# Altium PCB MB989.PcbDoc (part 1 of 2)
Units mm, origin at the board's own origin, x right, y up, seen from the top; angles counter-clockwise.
Board outline 88.27 x 52.07 mm, 2 copper layers (Top Layer, Bottom Layer), stack 1.6 mm thick; 68 components, 52 nets, 227 pads, 143 vias.
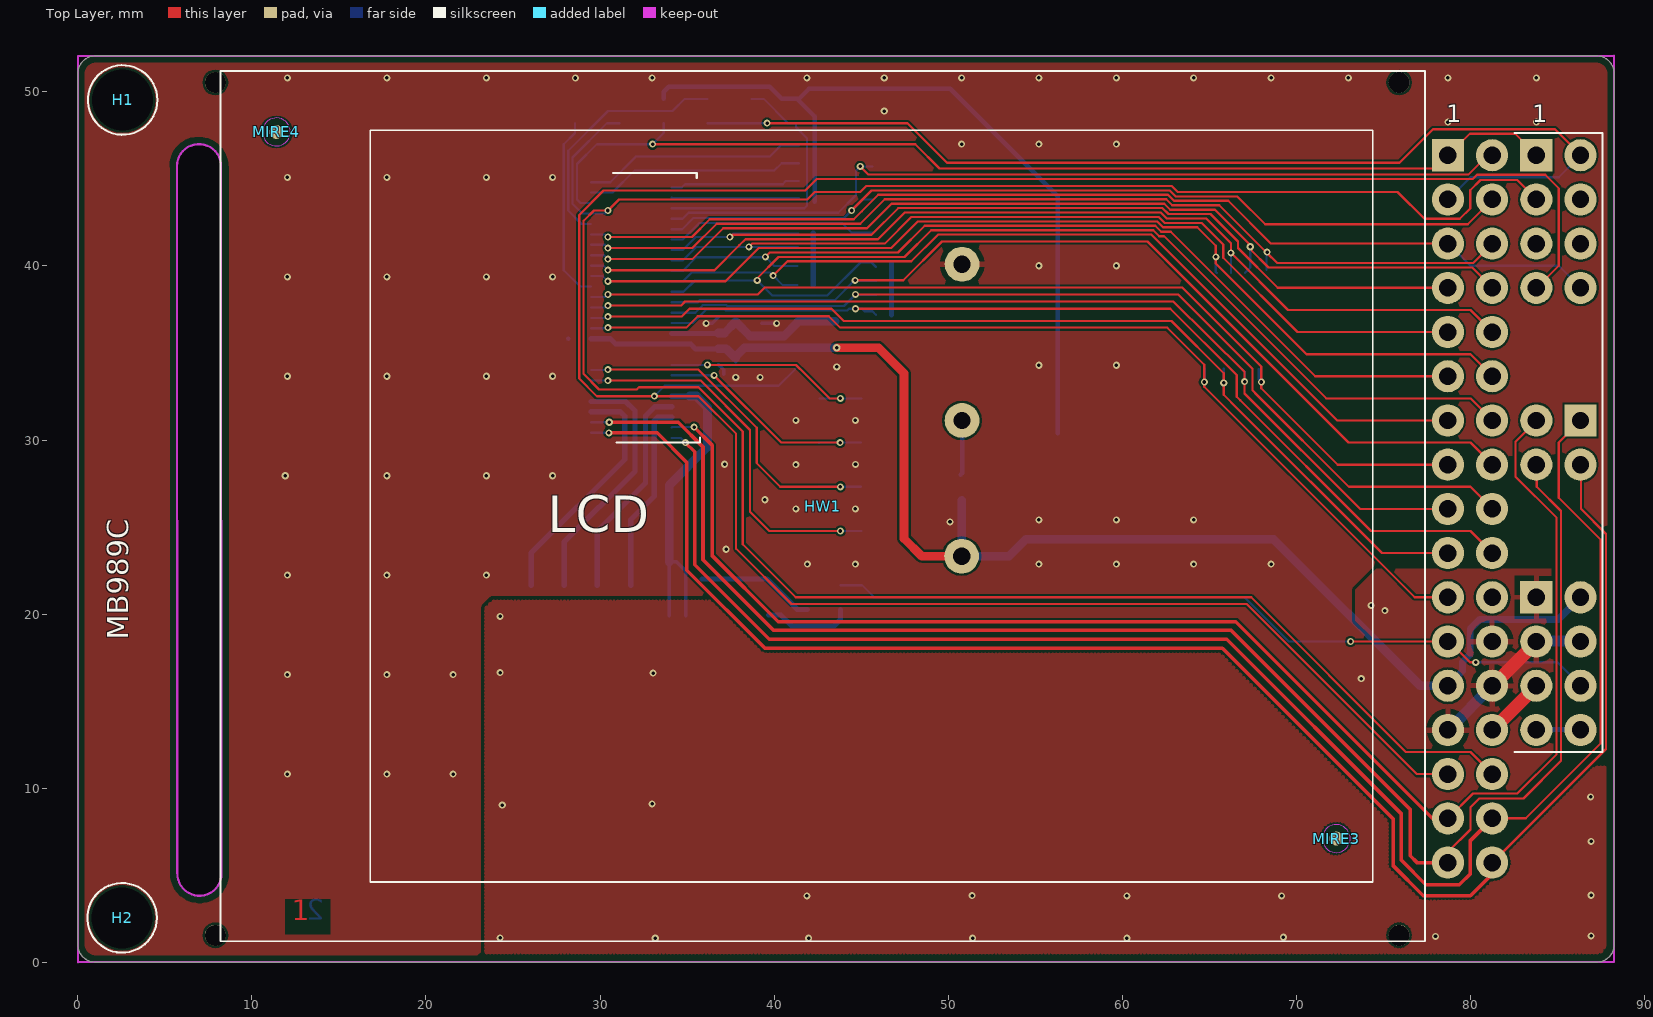
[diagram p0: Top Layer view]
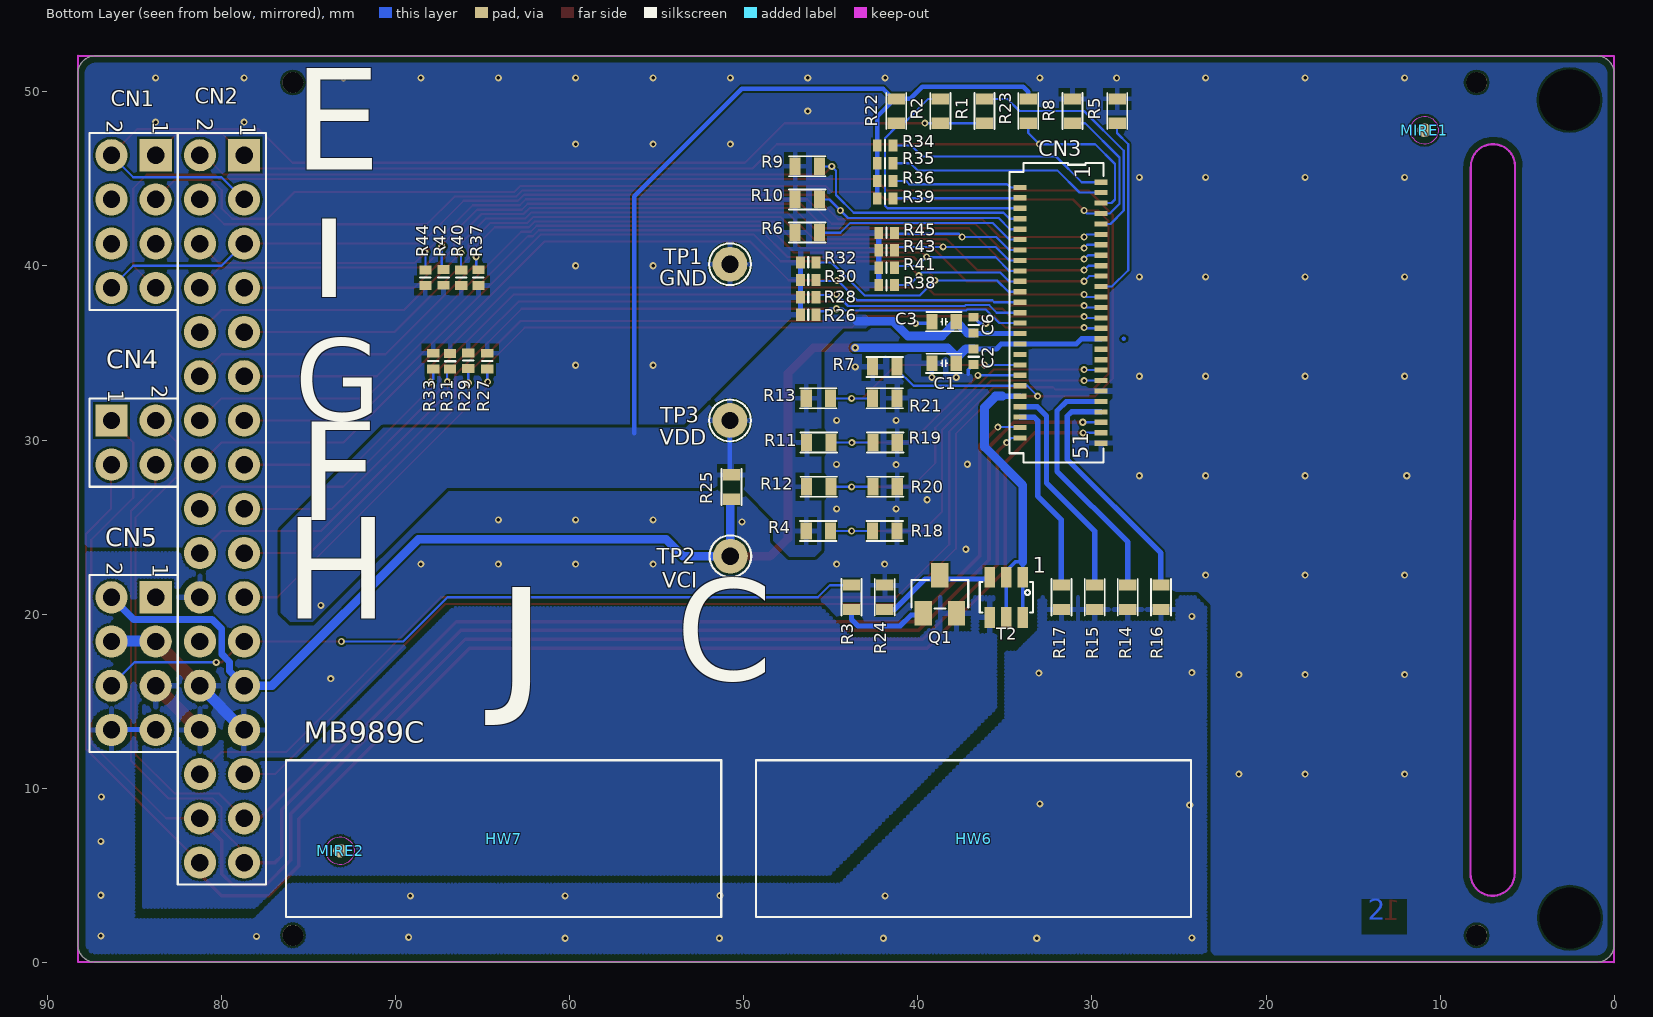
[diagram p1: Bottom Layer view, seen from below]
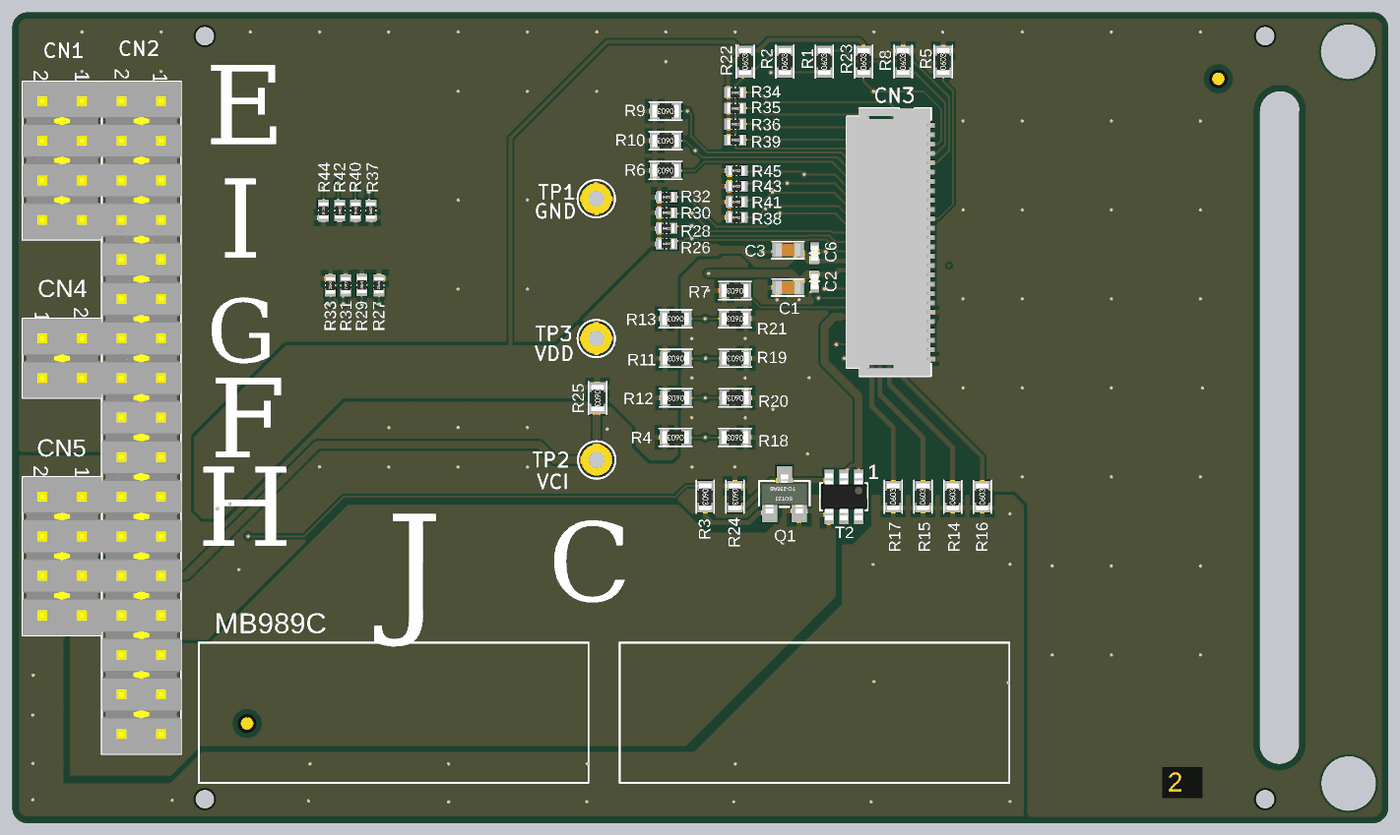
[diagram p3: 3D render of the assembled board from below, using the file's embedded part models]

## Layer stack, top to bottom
TopSolder: solder mask 0.01, Solder Resist, Dk 3.5
Top Layer: signal copper 0.035
Dielectric1: core 1.53, FR-4, Dk 4.8
Bottom Layer: signal copper 0.035
BottomSolder: solder mask 0.01, Solder Resist, Dk 3.5

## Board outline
0,1 0,51.07 cw(c1,51.07) 1,52.07 87.265,52.07 cw(c87.265,51.07) 88.265,51.07 88.265,1 cw(c87.265,1) 87.265,0 1,0 cw(c1,1)
cut-out: 5.69,45.727 5.715,45.702 5.715,5.085 ccw(c7,5.085) 7,3.8 ccw(c7,5.055) 8.255,5.055 8.255,45.702 ccw(c8.23,45.702) 8.23,45.727 ccw(c6.957,45.727) 6.957,47 6.9,47 ccw(c6.9,45.79) 5.69,45.79

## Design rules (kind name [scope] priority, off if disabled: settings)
BoardOutlineClearance "BOTTOM Silksreen clearence" [OnLayer('Bottom Overlay')] p1: gap=0 ignorepadtopadclearanceinfootprint=FALSE
BoardOutlineClearance "TOP Silksreen clearence" [OnLayer('Top Overlay')] p2: gap=0 ignorepadtopadclearanceinfootprint=FALSE
BoardOutlineClearance [All] p3: gap=0.4 ignorepadtopadclearanceinfootprint=FALSE
Clearance Clearance_ALIM [InNetClass('ALIM')] p1: gap=0.127 ignorepadtopadclearanceinfootprint=FALSE except(0.15: Track-Fill SMDPad-Fill THPad-Fill Via-Fill Fill-Fill; 0.2: Arc-Track Arc-THPad Track-Track Track-THPad SMDPad-SMDPad SMDPad-THPad THPad-THPad; 0.3: Track-Poly Poly-Poly)
Clearance [All] p2: gap=0.127 ignorepadtopadclearanceinfootprint=FALSE except(0.12: Track-THPad; 0.15: Track-Fill SMDPad-Fill THPad-Fill Fill-Fill; 0.2: Arc-THPad SMDPad-THPad THPad-THPad Poly-Poly)
ComponentClearance [All] p1 off: gap=0.025 collisioncheckmode=3 verticalgap=2540 showdistances=TRUE
DiffPairsRouting [InDifferentialPairClass('USB')] p1: maxlimit=0.226 minlimit=0.226 mostfreqgap=0.226 toplayer_minwidth=0.155 toplayer_maxwidth=0.155 toplayer_prefwidth=0.155 bottomlayer_minwidth=0.155 bottomlayer_maxwidth=0.155 bottomlayer_prefwidth=0.155 maxuncoupledlength=12.7
Height [All] p1 off: minheight=0 maxheight=100 prefheight=0.5
HoleSize [All] p1: absolutevalues=TRUE maxlimit=10 minlimit=0.1 maxpercent=80.000 minpercent=20.000
HoleToHoleClearance [All] p1: gap=0.25 allowstackedmicrovias=TRUE
MatchedLengths MatchedLengths_JTAG [All] p1: tolerance=10 checknetsindiffpair=FALSE checkdiffpairvsdiffpair=TRUE checkxsignals=TRUE checkothers=TRUE
MatchedLengths MatchedLengths_USB [InDifferentialPairClass('USB')] p2: tolerance=2.5 checknetsindiffpair=FALSE checkdiffpairvsdiffpair=TRUE checkxsignals=TRUE checkothers=TRUE
MatchedLengths MatchedLengths_SD_CARD [All] p3: tolerance=10 checknetsindiffpair=FALSE checkdiffpairvsdiffpair=TRUE checkxsignals=TRUE checkothers=TRUE
MatchedLengths MatchedLengths_SPI [InNetClass('SPI')] p4: tolerance=7 checknetsindiffpair=FALSE checkdiffpairvsdiffpair=TRUE checkxsignals=TRUE checkothers=TRUE
MinimumSolderMaskSliver [All] p1: minsoldermaskwidth=0
PlaneClearance [All] p1: clearance=0.5
PlaneConnect [All] p1: planeconnectstyle=Relief reliefexpansion=0.5 reliefentries=4 reliefconductorwidth=0.25 reliefairgap=0.25
PolygonConnect [All] p1: thpad.connectstyle=Relief thpad.reliefconductorwidth=0.3 thpad.reliefentries=4 thpad.polygonreliefangle="90 Angle" thpad.airgapwidth=0.3 smdpad.connectstyle=Relief smdpad.reliefconductorwidth=0.3 smdpad.reliefentries=4 smdpad.polygonreliefangle="90 Angle" smdpad.airgapwidth=0.3 via.connectstyle=Direct via.reliefconductorwidth=0.254 via.reliefentries=4 via.polygonreliefangle="90 Angle" via.airgapwidth=0.254
RoutingVias [All] p1: holewidth=0.2 width=0.45 viastyle="Through Hole" minholewidth=0.2 minwidth=0.4 maxholewidth=0.3 maxwidth=0.45
SilkToSilkClearance [All] p1: silktosilkclearance=0
SilkToSolderMaskClearance [IsPad] p1: minsilkscreentomaskgap=0 clearancetoexposedcopper=TRUE
SolderMaskExpansion [All] p1: expansion=0.102
Width Width_50_ohms [InNetClass('50 ohms')] p1: maxlimit=0.127 minlimit=0.127 preferedwidth=0.127 minimp=50.000000 maximp=50.000000 favimp=50.000000
Width Width_GND [InNetClass('GND')] p2: maxlimit=0.8 minlimit=0.19 preferedwidth=0.25 minimp=50.000000 maximp=50.000000 favimp=50.000000
Width Width_ALIM_150mA [InNetClass('ALIM_150mA')] p3: maxlimit=1 minlimit=0.25 preferedwidth=0.8 minimp=50.000000 maximp=50.000000 favimp=50.000000
Width Width_ALIM_200mA [InNetClass('ALIM_200mA')] p4: maxlimit=1 minlimit=0.25 preferedwidth=0.4 minimp=50.000000 maximp=50.000000 favimp=50.000000
Width Width_ALIM_500mA [InNetClass('ALIM_500mA')] p5: maxlimit=1 minlimit=0.25 preferedwidth=1 minimp=50.000000 maximp=50.000000 favimp=50.000000
Width Width_ALIM_1A [InNetClass('ALIM_1A')] p6: maxlimit=2 minlimit=0.25 preferedwidth=2 minimp=50.000000 maximp=50.000000 favimp=50.000000
Width Width_1 [All] p7: maxlimit=0.508 minlimit=0.127 preferedwidth=0.2 minimp=50.000000 maximp=50.000000 favimp=50.000000
20 further rules are at their usual default settings.

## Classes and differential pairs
net class ALIM_500mA: VDD
differential pair class USB: STLINK_USB_D USB_FS USB_FS_SB
net class "50 ohms": PD2
polygon class POLY_DIRECT_ALL: NETC906_2_L01_P192
component class U_ARDUINO_extension_connectors: HW25 HW26
component class U_Mechanical_Parts: HW03
component class U_ST_LINK_V2-1: SB100
component class U_STM32_microcontroller_IOs: HW17 HW18
component class U_USB_Type_C: HW23 HW24
net class GND: GND
differential pair STLINK_USB_D: +"" -""
differential pair USB_FS: +"" -""

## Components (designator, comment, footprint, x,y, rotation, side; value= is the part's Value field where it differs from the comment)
C1 "Capacitor" C0603 38.5,34.4 r180 bottom value=4.7uF
C2 "Capacitor" C0402 36.8,34.786 r90 bottom value=100nF
C3 "Capacitor" C0603 38.5,36.8 r180 bottom value=4.7uF
C6 "Capacitor" C0402 36.8,36.6 r270 bottom value=100nF
CN1 "Header 4x2_LCD_IO_MB989_S" CON_SAMTEC_TSW-104-07-X-D_INV 85.065,42.552 r270 bottom
CN2 "Header 17x2_LCD_TFT_MB989_P" CON_SAMTEC_TSW-117-07-X-D_INV 79.985,26.042 r270 bottom value=TFT_LCD_MB989_P_HEADER
CN3 "SOCKET_MRE028_xxxxx-51P-TP-A" CON_OMRON_XF2B-5145-31A_INV 31.802,37.315 r90 bottom value="MRE028_xxxxx-51P-TP-A TFT LCD SOCKET"
CN4 "Header 2x2_LCD_BACKLIGHT_MB989_S" CON_SAMTEC_TSW-102-07-X-D 85.065,29.852 r270 bottom
CN5 "Header 4x2_LCD_PWR_MB989_S" CON_SAMTEC_TSW-104-07-X-D_INV 85.065,17.152 r270 bottom
H1 "POSITION HOLE" NPTH_350 2.567,49.537 r0 top
H2 "POSITION HOLE" NPTH_350 2.54,2.547 r0 top
HW1 "LCD_MODULE" LCD_DRAWING_PROJET-MB989 42.8,26.2 r180 top value=MRE028-8347I-51P-TP-A
HW6 "STICKER_BOARD_REF" STICKER_25X9 36.8,7.1 r180 bottom value=SN
HW7 "STICKER_BOARD_CPN" STICKER_25X9 63.8,7.1 r180 bottom value=CPN
MIRE1 "Comment" MIRE_PLACE_SMD_0P8MM 10.9,47.8 r0 bottom
MIRE2 "Comment" MIRE_PLACE_SMD_0P8MM 73.2,6.4 r0 bottom
MIRE3 "Comment" MIRE_PLACE_SMD_0P8MM 72.3,7.1 r180 top
MIRE4 "Comment" MIRE_PLACE_SMD_0P8MM 11.4,47.7 r180 top
Q1 "PNP_SOT23" ICC_SOT23-3L_H1P12 38.735,21.14 r180 bottom value=BC807
R1 "Resistor" R0603 36.17,48.902 r90 bottom value=0R
R2 "Resistor" R0603 38.71,48.902 r90 bottom value=0R
R3 "Resistor" R0603 43.815,20.962 r270 bottom value=1K
R4 "Resistor" R0603 45.72,24.772 r0 bottom value=4K7
R5 "Resistor" R0603 28.55,48.902 r90 bottom value=4K7
R6 "Resistor" R0603 46.355,41.917 r0 bottom value=4K7
R7 "Resistor" R0603 41.9,34.2 r0 bottom value=4K7
R8 "Resistor" R0603 31.115,48.902 r90 bottom value=4K7
R9 "Resistor" R0603 46.355,45.727 r0 bottom value=4K7
R10 "Resistor" R0603 46.355,43.822 r0 bottom value=4K7
R11 "Resistor" R0603 45.695,29.852 r0 bottom value=4K7
R12 "Resistor" R0603 45.695,27.312 r0 bottom value=4K7
R13 "Resistor" R0603 45.72,32.392 r0 bottom value=4K7
R14 "Resistor" R0603 27.94,20.962 r90 bottom value=75R
R15 "Resistor" R0603 29.845,20.962 r90 bottom value=75R
R16 "Resistor" R0603 26.035,20.962 r90 bottom value=75R
R17 "Resistor" R0603 31.75,20.962 r90 bottom value=75R
R18 "Resistor" R0603 41.907,24.772 r0 bottom value=4K7
R19 "Resistor" R0603 41.885,29.852 r0 bottom value=4K7
R20 "Resistor" R0603 41.885,27.312 r0 bottom value=4K7
R21 "Resistor" R0603 41.907,32.392 r0 bottom value=4K7
R22 "Resistor" R0603 41.25,48.902 r90 bottom value=4K7
R23 "Resistor" R0603 33.655,48.902 r90 bottom value=4K7
R24 "Resistor" R0603 41.91,20.962 r270 bottom value=4K7
R25 "Resistor" R0603 50.717,27.3 r270 bottom value=0R
R26 "Resistor" R0402 46.3,37.2 r180 bottom value=10K
R27 "Resistor" R0402 64.742,34.537 r270 bottom value=10K
R28 "Resistor" R0402 46.3,38.2 r180 bottom value=10K
R29 "Resistor" R0402 65.837,34.558 r270 bottom value=10K
R30 "Resistor" R0402 46.3,39.2 r180 bottom value=10K
R31 "Resistor" R0402 66.878,34.526 r270 bottom value=10K
R32 "Resistor" R0402 46.3,40.2 r180 bottom value=10K
R33 "Resistor" R0402 67.85,34.531 r270 bottom value=10K
R34 "Resistor" R0402 41.885,46.921 r180 bottom value=10K
R35 "Resistor" R0402 41.885,45.905 r180 bottom value=10K
R36 "Resistor" R0402 41.885,44.889 r180 bottom value=10K
R37 "Resistor" R0402 65.253,39.334 r90 bottom value=10K
R38 "Resistor" R0402 41.8,38.9 r180 bottom value=10K
R39 "Resistor" R0402 41.885,43.873 r180 bottom value=10K
R40 "Resistor" R0402 66.243,39.326 r90 bottom value=10K
R41 "Resistor" R0402 41.8,39.9 r180 bottom value=10K
R42 "Resistor" R0402 67.259,39.345 r90 bottom value=10K
R43 "Resistor" R0402 41.8,40.9 r180 bottom value=10K
R44 "Resistor" R0402 68.301,39.326 r90 bottom value=10K
R45 "Resistor" R0402 41.8,41.9 r180 bottom value=10K
T2 "FDC606P" MOS_SOT23-6L 34.925,20.962 r0 bottom
TP1 "Test_Point_PTH_1mm_2mm" TP_PTH_1MM_2MM 50.8,40.1 r180 bottom value=GND
TP2 "Test_Point_PTH_1mm_2mm" TP_PTH_1MM_2MM 50.775,23.324 r180 bottom value=VCI
TP3 "Test_Point_PTH_1mm_2mm" TP_PTH_1MM_2MM 50.8,31.122 r180 bottom value=VDD

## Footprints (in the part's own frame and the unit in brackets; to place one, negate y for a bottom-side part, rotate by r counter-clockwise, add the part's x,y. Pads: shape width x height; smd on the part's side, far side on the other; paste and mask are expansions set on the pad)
C0402 [mm]
  rect 0.51x0.56 smd mask+0.05: 1(-0.45,0) 2(0.45,0)
  silkscreen extent 0,-0.3 0,0.3, body extent -0.5,-0.3 0.5,0.3, height 0.4
C0603 [mm]
  rect 0.64x0.89 smd mask+0.05: 1(-0.7,0) 2(0.7,0)
  silkscreen extent -1.05,-0.55 1.02,0.55, body extent -0.9,-0.5 0.9,0.5, height 1.4
CON_OMRON_XF2B-5145-31A_INV [mm] "MCD-01657"
  rect 0.3x0.75 smd mask+0.05: 1(7.5,-2.325) 2(7.2,2.325) 3(6.9,-2.325) 4(6.6,2.325) 5(6.3,-2.325) 6(6,2.325) 7(5.7,-2.325) 8(5.4,2.325) 9(5.1,-2.325) 10(4.8,2.325) 11(4.5,-2.325) 12(4.2,2.325) 13(3.9,-2.325) 14(3.6,2.325) 15(3.3,-2.325) 16(3,2.325) 17(2.7,-2.325) 18(2.4,2.325) 19(2.1,-2.325) 20(1.8,2.325) 21(1.5,-2.325) 22(1.2,2.325) 23(0.9,-2.325) 24(0.6,2.325) 25(0.3,-2.325) 26(0,2.325) 27(-0.3,-2.325) 28(-0.6,2.325) 29(-0.9,-2.325) 30(-1.2,2.325) 31(-1.5,-2.325) 32(-1.8,2.325) 33(-2.1,-2.325) 34(-2.4,2.325) 35(-2.7,-2.325) 36(-3,2.325) 37(-3.3,-2.325) 38(-3.6,2.325) 39(-3.9,-2.325) 40(-4.2,2.325) 41(-4.5,-2.325) 42(-4.8,2.325) 43(-5.1,-2.325) 44(-5.4,2.325) 45(-5.7,-2.325) 46(-6,2.325) 47(-6.3,-2.325) 48(-6.6,2.325) 49(-6.9,-2.325) 50(-7.2,2.325) 51(-7.5,-2.325)
  silkscreen extent -8.6,-2.47 8.6,2.93, body extent -8.6,-6.47 8.6,2.97, height 4.9
CON_SAMTEC_TSW-102-07-X-D [mm] "MCD-01665"
  rect 1.85x1.85 / inner round 1.85 / far side rect 1.85x1.85 hole 1 mask+0.05: 1(-1.27,-1.27)
  round 1.85 hole 1 mask+0.05: 2(-1.27,1.27) 3(1.27,-1.27) 4(1.27,1.27)
  silkscreen extent -2.54,-2.54 2.54,2.54, body extent -2.54,-2.54 2.55,2.54, height 8.38
CON_SAMTEC_TSW-104-07-X-D_INV [mm] "MCD-01658"
  rect 1.85x1.85 / inner round 1.85 / far side rect 1.85x1.85 hole 1 mask+0.05: 1(-3.81,1.27)
  round 1.85 hole 1 mask+0.05: 2(-3.81,-1.27) 3(-1.27,1.27) 4(-1.27,-1.27) 5(1.27,1.27) 6(1.27,-1.27) 7(3.81,1.27) 8(3.81,-1.27)
  silkscreen extent -5.08,-2.54 5.08,2.54, body extent -5.08,-2.54 5.08,2.54, height 8.38
CON_SAMTEC_TSW-117-07-X-D_INV [mm]
  rect 1.85x1.85 / inner round 1.85 / far side rect 1.85x1.85 hole 1 mask+0.05: 1(-20.32,1.27)
  round 1.85 hole 1 mask+0.05: 2(-20.32,-1.27) 3(-17.78,1.27) 4(-17.78,-1.27) 5(-15.24,1.27) 6(-15.24,-1.27) 7(-12.7,1.27) 8(-12.7,-1.27) 9(-10.16,1.27) 10(-10.16,-1.27) 11(-7.62,1.27) 12(-7.62,-1.27) 13(-5.08,1.27) 14(-5.08,-1.27) 15(-2.54,1.27) 16(-2.54,-1.27) 17(0,1.27) 18(0,-1.27) 19(2.54,1.27) 20(2.54,-1.27) 21(5.08,1.27) 22(5.08,-1.27) 23(7.62,1.27) 24(7.62,-1.27) 25(10.16,1.27) 26(10.16,-1.27) 27(12.7,1.27) 28(12.7,-1.27) 29(15.24,1.27) 30(15.24,-1.27) 31(17.78,1.27) 32(17.78,-1.27) 33(20.32,1.27) 34(20.32,-1.27)
  silkscreen extent -21.59,-2.54 21.59,2.54, body extent -21.59,-2.55 21.6,2.54, height 8.38
ICC_SOT23-3L_H1P12 [mm]
  rect 1x1.4 smd mask+0.05: 1(-0.95,-1.1) 2(0.95,-1.1) 3(0,1.1)
  silkscreen extent -1.63,-0.82 1.63,0.82, body extent -1.56,-1.25 1.56,1.25, height 1.12
LCD_DRAWING_PROJET-MB989 [mm] "MCD-01419"
  silkscreen extent -34.6,-25 34.6,25, body extent -34.6,-25 35.96,25, height 3.62
MIRE_PLACE_SMD_0P8MM [mm]
  round 0.8 smd paste-10 mask+0.2: 1(0,0)
  Top Layer keep-out circle w0.01: c0,0 r0.804
MOS_SOT23-6L [mm]
  rect 0.6x1.2 smd mask+0.05: 1(-0.95,-1.15) 2(0,-1.15) 3(0.95,-1.15) 4(0.95,1.15) 5(0,1.15) 6(-0.95,1.15)
  silkscreen extent -1.53,-0.87 1.53,0.87, body extent -1.52,-1.5 1.52,1.5, height 1.3
NPTH_350 [mm]
  round 0 hole 3.5 unplated mask+0.05: 1(0,0)
  silkscreen extent -2,-2 2,2
R0402 [mm]
  rect 0.51x0.7 smd mask+0.05: 1(-0.45,0) 2(0.45,0)
  silkscreen extent 0,-0.3 0,0.3, body extent -0.52,-0.3 0.52,0.3, height 0.4
R0603 [mm]
  rect 0.64x1 smd mask+0.05: 1(-0.7,0) 2(0.7,0)
  silkscreen extent -1.05,-0.58 1.05,0.58, body extent -0.9,-0.5 0.9,0.5, height 0.56
STICKER_25X9 [mm] "Sticker 25mm x 9mm"
  silkscreen extent -12.5,-4.5 12.5,4.5
TP_PTH_1MM_2MM [mm] "MCD-01506"
  round 2 hole 1 mask+0.05: 1(0,0)
  silkscreen extent -1.2,-1.2 1.2,1.2

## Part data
C1 C3: library part MCD-01121, "Capacitor, MLCC, 4.7µF, 10V, X5R, 20%, 0603, T=0,8mm", Manufacturer=MURATA, Manufacturer_Part_Number=GRM188R61A475ME15, Package=C0603
C2 C6: library part MCD-00006, "Capacitor, MLCC, 100nF, 16V, X7R, 10%, 0402, T=0.5mm", Alternate_Manufacturer=MURATA, Alternate_Manufacturer_Part_Number=GCM155R71C104KA55D, Manufacturer=YAGEO, Manufacturer_Part_Number=CC0402KRX7R7BB104, Package=C0402
CN1: library part MCD-01658, "Header, 4x1, 2,54mm, VR, TH, Height 5.84mm/2.54mm, for TFT LCD MODULE MB989_S: pinning inverted", Manufacturer=SAMTEC, Manufacturer_Part_Number=TSW-104-07-x-D
CN2: library part MCD-01343, "Header, 17x2, 2,54mm, VR, TH, Height 5.84mm/2.54mm for TFT_LCD MB989_P", Manufacturer=SAMTEC, Manufacturer_Part_Number=TSW-117-07-x-D
CN3: library part MCD-01657, "FCP connector for MRE028_xxxxx-51P-TP-A TFT LCD 2.8inch 320x240", Manufacturer=OMRON, Manufacturer_Part_Number=XF2B-5145-31A
CN4: library part MCD-01665, "Header, 2x2, 2,54mm, VR, TH, Height 5.84mm/2.54mm, for TFT LCD MB989_P: Backlight", Manufacturer=SAMTEC, Manufacturer_Part_Number=TSW-102-07-x-D
CN5: library part MCD-01659, "Header, 4x2, 2,54mm, VR, TH, Height 5.84mm/2.54mm for TFT LCD MODULE MB989_S: pinning inverted", Manufacturer=SAMTEC, Manufacturer_Part_Number=TSW-104-07-x-D
H1 H2: library part MCD-01368, "POSITION HOLE C3R5D3R5", Manufacturer=n/a
HW1: library part MCD-01419, "Display 2.8inch SPI or 16-bit parallel", Manufacturer="SHANGHAI MOORING ELECTRONICS TECHNOLOGY", Manufacturer_Part_Number=MRE028-8347I-51P-TP-A
HW6: library part MCD-00235, "Sticker to mention board reference + serial number", Manufacturer=n/a
HW7: library part MCD-00547, "Sticker to mention board CPN code", Manufacturer=n/a
Q1: library part MCD-01527, "Transistor Bipolar PNP, 45V, 500mA, 100MHz, 300mW, SOT23-3", Alternate_Manufacturer=NXP, Alternate_Manufacturer_Part_Number=BC807, Manufacturer=NEXPERIA
R1 R2 R25: library part MCD-00056, "Resistor,0R,0603,5%,1/10W", Manufacturer=YAGEO, Manufacturer_Part_Number=RC0603JR-070RL, Package=R0603
R3: library part MCD-00070, "Resistor,1K,0603,1%,1/10W", Manufacturer=YAGEO, Manufacturer_Part_Number=RC0603FR-071KL, Package=R0603
R4 R5 R6 R7 R8 R9 R10 R11 R12 R13 R18 R19 R20 R21 R22 R23 R24: library part MCD-00219, "Resistor,4K7,0603,1%,1/10W", Manufacturer=YAGEO, Manufacturer_Part_Number=RC0603FR-074K7L, Package=R0603
R14 R15 R16 R17: library part MCD-00516, "Resistor,75R,0603,1%,1/10W", Manufacturer=YAGEO, Manufacturer_Part_Number=RC0603FR-0775RL, Package=R0603
R26 R27 R28 R29 R30 R31 R32 R33 R34 R35 R36 R37 R38 R39 R40 R41 R42 R43 R44 R45: library part MCD-00053, "Resistor,10K,0402,1%,1/16W", Manufacturer=YAGEO, Manufacturer_Part_Number=RC0402FR-0710KL, Package=R0402
T2: library part MCD-01655, "MOSFET, P-Channel , Vgs(th): -1.5V, Id: -6A, Vds(max): -12V, Vgs(max): +/-8V, Rdson:26mohm@Vgs=-4.5V", Manufacturer="ON SEMICONDUCTOR", Package=SOT23-6L
TP1 TP2 TP3: library part MCD-01506, "Test Point trought hole 1mm/2mm", Manufacturer=n/a

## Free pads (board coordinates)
  round 1.2 hole 1.2 unplated: 0(75.912,1.542) 1(7.897,1.542) 2(7.897,50.542) 3(75.912,50.542)
  round 0.508 on Mech16: 1(31.577,-104.696) 1(80.424,-104.696)

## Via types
v1: diameter 0.406, hole 0.203, Top Layer to Bottom Layer, tented both sides, 143 vias

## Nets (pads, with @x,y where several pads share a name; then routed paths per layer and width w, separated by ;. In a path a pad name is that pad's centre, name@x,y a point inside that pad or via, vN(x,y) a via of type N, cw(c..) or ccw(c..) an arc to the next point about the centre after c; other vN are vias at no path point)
BL_Control: CN2.23 CN5.6 R3.1 | length 44.9
  Top Layer w0.127: v1(73.127,18.422) CN2.23@78.715,18.422 78.791,18.422 79.984,17.229 v1(80.314,17.229)
  Bottom Layer w0.127: R3.1@43.815,21.662 45.06,21.661 45.758,20.962 67.031,20.962 69.571,18.422 v1(73.127,18.422) ; v1(80.314,17.229) 85.013,17.229 86.347,15.895 CN5.6@86.36,15.882
BLGND: CN2.22 CN5.7 CN5.8 R14.1 R15.1 R16.1 R17.1 | length 2.5
  Bottom Layer w0.305: CN5.7@83.82,13.368 CN5.8@86.36,13.368
  other v1: 33.172,1.372 41.986,1.372 51.41,1.372 60.274,1.372 24.257,1.397 69.264,1.43 78.002,1.48 86.943,1.506 41.885,3.81 60.274,3.81 69.164,3.81 51.383,3.817 86.943,3.843 86.943,6.941 24.384,9.017 32.995,9.093 86.919,9.5 33.045,16.612 24.257,16.637 24.257,19.863
BLVDD: CN2.28 CN5.5 Q1.2 T2.4 | length 3.6
  Top Layer w0.305: CN5.5@83.82,15.882 CN5.5@83.82,15.908
  Top Layer w0.762: CN2.28@81.28,13.342 CN5.5@83.82,15.882
CSn: CN1.1 CN2.1 CN3.5 R23.1 | length 61.9
  Top Layer w0.127: v1(33.02,46.997) 48.108,46.997 49.505,45.6 77.978,45.6 78.727,46.35 79.978,47.6 82.582,47.6 83.807,46.375 CN1.1@83.82,46.362
  Bottom Layer w0.127: CN3.5@29.477,43.615 28.884,43.615 28.677,43.822 28.677,45.854 29.82,46.997 v1(33.02,46.997) 33.662,47.639 33.662,48.202 R23.1@33.662,48.205
DotClk: CN3.2 R36.2 | length 7.5
  Bottom Layer w0.127: CN3.2@34.127,44.515 34.704,44.515 34.881,44.692 40.494,44.692 40.691,44.889 R36.2@41.435,44.889
Enable: CN3.1 R34.2 | length 12.8
  Bottom Layer w0.127: CN3.1@29.477,44.815 30.589,44.815 32.066,46.292 39.757,46.292 40.386,46.921 R34.2@41.435,46.921
GND: C1.1 C2.1 C3.1 C6.1 CN2.26 CN2.27 CN3.41 CN3.51 CN5.3 CN5.4 R5.2 R6.2 R7.2 R8.2 R9.2 R10.2 R18.1 R19.1 R20.1 R21.1 R24.1 R26.1 R27.1 R28.1 R29.1 R30.1 R31.1 R32.1 R33.1 R37.1 R38.1 R40.1 R41.1 R42.1 R43.1 R44.1 R45.1 TP1.1 | length 18.8
  Top Layer w0.762: CN2.26@81.28,15.882 83.82,18.422 CN5.3@83.82,18.448
  Bottom Layer w0.203: v1(36.1,36.7) 36.45,36.7 C6.1@36.8,37.05 ; C2.1@36.8,34.336 37.1,34.036 37.1,33.77 ; C3.1@39.3,36.7 v1(40.151,36.7)
  Bottom Layer w0.3: R38.1@42.25,38.9 R41.1@42.25,39.9 R43.1@42.25,40.9 R45.1@42.25,41.9 ; R26.1@46.75,37.2 R28.1@46.75,38.2 R30.1@46.75,39.2 R32.1@46.75,40.2
  Bottom Layer w0.305: CN2.26@81.28,15.882 CN2.26@81.28,16.517
  Bottom Layer w0.635: CN2.27@78.74,13.342 CN2.26@81.28,15.882 ; CN5.3@83.82,18.448 CN5.4@86.36,18.448
  other v1: 12.04,10.802 17.755,10.802 21.565,10.802 73.735,16.289 12.04,16.517 17.755,16.517 21.565,16.517 12.04,22.232 17.755,22.232 23.47,22.232 41.91,22.867 44.677,22.867 55.22,22.867 59.665,22.867 64.11,22.867 68.555,22.867 37.25,23.724 50.108,25.3 55.22,25.407 59.665,25.407 64.11,25.407 41.25,26.042 44.677,26.042 39.472,26.568 11.913,27.947 17.755,27.947 23.47,27.947 27.28,27.947 41.25,28.582 44.679,28.6 37.159,28.608 41.25,31.122 44.677,31.122 37.8,33.6 39.2,33.6 12.04,33.662 17.755,33.662 23.47,33.662 27.28,33.662 43.6,34.2 55.22,34.297 59.665,34.297 12.04,39.377 17.755,39.377 23.47,39.377 27.28,39.377 55.22,40.012 59.665,40.012 12.04,45.092 17.755,45.092 23.47,45.092 27.28,45.092 50.775,46.997 55.22,46.997 59.665,46.997 78.715,48.267 83.795,48.267 46.33,48.902 28.582,50.8 12.04,50.807 17.755,50.807 23.47,50.807 32.995,50.807 41.885,50.807 46.33,50.807 50.775,50.807 55.22,50.807 59.665,50.807 64.11,50.807 68.555,50.807 73,50.807 78.715,50.807 83.795,50.807
HSYNC: CN3.3 R35.2 | length 12.7
  Bottom Layer w0.127: CN3.3@29.477,44.215 30.716,44.215 31.993,45.492 40.024,45.492 40.437,45.905 R35.2@41.435,45.905
IM0: CN3.39 R4.1 R18.2 | length 23.1
  Top Layer w0.127: v1(30.448,33.415) 35.782,33.415 38.617,30.58 38.617,25.881 39.726,24.772 v1(43.815,24.772)
  Bottom Layer w0.127: CN3.39@29.477,33.415 v1(30.448,33.415) ; R18.2@42.607,24.765 43.815,24.765 R4.1@45.014,24.765
IM1: CN3.38 R11.1 R19.2 | length 13.7
  Top Layer w0.127: v1(36.551,33.715) 36.551,33.708 40.407,29.852 v1(43.79,29.852)
  Bottom Layer w0.127: CN3.38@34.127,33.715 v1(36.551,33.715) ; R19.2@42.585,29.845 42.588,29.849 42.592,29.852 v1(43.79,29.852) R11.1@44.995,29.852 R11.1@44.996,29.852
IM2: CN3.37 R12.1 R20.2 | length 20.7
  Top Layer w0.127: v1(30.455,34.043) 35.662,34.043 39.002,30.703 39.002,28.671 40.361,27.312 v1(43.815,27.312)
  Bottom Layer w0.127: CN3.37@29.477,34.015 30.427,34.015 v1(30.455,34.043) ; R20.2@42.589,27.312 v1(43.815,27.312) R12.1@44.995,27.312 R12.1@44.996,27.312
IM3: CN3.36 R13.1 R21.2 | length 12.9
  Top Layer w0.127: v1(36.17,34.315) 41.257,34.315 41.755,33.817 43.18,32.392 v1(43.815,32.392)
  Bottom Layer w0.127: CN3.36@34.127,34.315 v1(36.17,34.315) ; R21.2@42.614,32.392 v1(43.815,32.392) R13.1@45.02,32.392 R13.1@45.021,32.392
NetCN3_42: CN3.42 T2.1 T2.2 T2.5 T2.6 | length 18.9
  Bottom Layer w0.203: T2.6@33.975,19.912 33.975,22.994 34.406,22.994 34.925,22.475 T2.5@34.925,19.912
  Bottom Layer w0.305: CN3.42@34.127,32.515 35.15,32.515
  Bottom Layer w0.508: 33.975,22.994 33.975,27.404 36.17,29.598 36.17,31.884 35.535,32.519 35.154,32.519 35.15,32.515
NetCN3_43: CN3.43 R14.2 | length 14.5
  Bottom Layer w0.305: R14.2@27.94,21.662 R14.2@27.94,21.662 27.94,24.137 32.004,28.201 32.004,31.681 31.47,32.215 CN3.43@29.477,32.215
NetCN3_44: CN3.44 R15.2 | length 12.6
  Bottom Layer w0.305: R15.2@29.845,21.662 R15.2@29.845,21.662 29.845,24.772 32.608,27.535 32.608,31.371 33.153,31.915 CN3.44@34.127,31.915
NetCN3_45: CN3.45 R16.2 | length 14
  Bottom Layer w0.305: R16.2@26.042,21.662 26.042,23.509 31.42,28.887 31.42,31.376 31.181,31.615 CN3.45@29.477,31.615
NetCN3_46: CN3.46 R17.2 | length 11.1
  Bottom Layer w0.305: R17.2@31.757,21.662 31.757,25.414 32.705,26.362 33.122,26.779 33.122,31.122 33.315,31.315 CN3.46@34.127,31.315
NetQ1_1: Q1.1 R3.2 | length 5.1
  Bottom Layer w0.305: Q1.1@39.688,19.946 40.386,19.946 41.021,19.311 43.434,19.311 43.815,19.692 R3.2@43.815,20.262 R3.2@43.815,20.264
NetQ1_3: Q1.3 R24.2 T2.3 | length 6.8
  Bottom Layer w0.305: T2.3@35.875,22.012 39.59,22.012 41.34,20.262 R24.2@41.903,20.262
PD0: CN3.12 R6.1 | length 12.2
  Bottom Layer w0.127: CN3.12@34.127,41.515 34.752,41.515 35.712,42.476 43.891,42.476 44.457,41.91 45.655,41.91 R6.1@45.658,41.91
PD1: CN2.6 CN3.13 R44.2 | length 56.1
  Top Layer w0.127: v1(30.455,41.028) 35.306,41.028 36.703,42.425 44.958,42.425 46.365,43.832 62.528,43.832 62.872,43.489 65.586,43.489 68.282,40.792 v1(68.326,40.792) 68.326,40.749 68.908,40.167 80.165,40.167 81.267,41.27 CN2.6@81.28,41.282
  Bottom Layer w0.127: CN3.13@29.477,41.215 30.268,41.215 v1(30.455,41.028) ; R44.2@68.301,39.776 68.301,40.792 68.301,40.818 v1(68.326,40.792)
PD2: CN2.7 CN3.14 R45.2 | length 51.8
  Top Layer w0.127: v1(37.465,41.663) 37.592,41.79 45.593,41.79 47.127,43.324 62.318,43.324 62.661,42.981 65.078,42.981 66.65,41.409 66.65,41.028 68.936,38.742 CN2.7@78.715,38.742 CN2.7@78.74,38.742
  Bottom Layer w0.127: CN3.14@34.127,40.915 34.759,40.915 35.507,41.663 v1(37.465,41.663) 37.649,41.847 R45.2@41.409,41.847
PD3: CN2.8 CN3.15 R42.2 | length 57
  Top Layer w0.127: v1(30.455,40.393) 35.306,40.393 37.084,42.171 45.339,42.171 46.746,43.578 62.423,43.578 62.767,43.235 65.332,43.235 67.361,41.206 v1(67.361,41.104) 67.361,40.952 68.402,39.911 80.112,39.911 81.267,38.755 CN2.8@81.28,38.742
  Bottom Layer w0.127: CN3.15@29.477,40.615 30.233,40.615 v1(30.455,40.393) ; R42.2@67.05,39.593 67.255,39.799 67.361,39.904 v1(67.361,41.104)
PD4: CN2.9 CN3.16 R43.2 | length 52
  Top Layer w0.127: v1(38.548,41.095) 38.735,41.282 46.355,41.282 47.889,42.816 62.108,42.816 62.451,42.473 64.57,42.473 65.761,41.282 ; 65.563,41.48 65.811,41.231 65.811,40.469 70.079,36.202 CN2.9@78.715,36.202 CN2.9@78.74,36.202
  Bottom Layer w0.127: CN3.16@34.127,40.315 34.755,40.315 35.535,41.095 v1(38.548,41.095) 41.342,41.095 R43.2@41.409,41.028
PD5: CN2.10 CN3.17 R40.2 | length 57.6
  Top Layer w0.127: v1(30.455,39.758) 36.576,39.758 38.002,41.185 38.354,41.536 45.974,41.536 47.508,43.07 62.213,43.07 62.556,42.727 64.824,42.727 66.25,41.301 v1(66.25,40.755) 69.533,37.472 80.01,37.472 81.267,36.215 CN2.10@81.28,36.202
  Bottom Layer w0.127: CN3.17@29.477,40.015 30.198,40.015 v1(30.455,39.758) ; R40.2@66.25,39.593 66.25,39.776 v1(66.25,40.755)
PD6: CN2.11 CN3.18 R41.2 | length 51.3
  Top Layer w0.127: v1(39.497,40.52) 39.751,40.774 47.117,40.774 48.651,42.308 61.897,42.308 62.241,41.965 62.792,41.965 71.095,33.662 CN2.11@78.715,33.662 CN2.11@78.74,33.662
  Bottom Layer w0.127: CN3.18@34.127,39.715 34.755,39.715 35.535,40.495 39.472,40.495 v1(39.497,40.52) ; v1@39.522,40.495 40.017,40 R41.2@41.35,40
PD7: CN2.12 CN3.19 R37.2 | length 58.6
  Top Layer w0.127: v1(30.455,39.123) 37.211,39.123 39.116,41.028 46.736,41.028 48.27,42.562 62.002,42.562 62.346,42.219 64.316,42.219 65.38,41.155 v1(65.38,40.52) 65.38,40.139 70.587,34.932 80.01,34.932 81.267,33.675 CN2.12@81.28,33.662
  Bottom Layer w0.127: CN3.19@29.477,39.415 30.163,39.415 v1(30.455,39.123) ; v1(65.38,40.52) 65.38,39.784 65.38,39.663 R37.2@65.45,39.593
PD8: CN2.13 CN3.20 R38.2 | length 51.9
  Top Layer w0.127: v1(39.948,39.447) 40.767,40.266 47.879,40.266 49.413,41.8 61.687,41.8 72.365,31.122 CN2.13@78.715,31.122 CN2.13@78.74,31.122
  Bottom Layer w0.127: CN3.20@34.127,39.115 34.765,39.115 35.281,39.631 39.764,39.631 v1(39.948,39.447) 40.495,38.9 R38.2@41.35,38.9
PD9: CN3.21 R5.1 | length 10.7
  Bottom Layer w0.127: R5.1@28.557,48.205 28.557,48.202 28.557,47.639 27.915,46.997 27.915,39.758 28.858,38.815 CN3.21@29.477,38.815
PD10: CN2.14 CN3.22 R32.2 | length 61.2
  Top Layer w0.127: v1@39.034,39.295 40.259,40.52 47.498,40.52 49.032,42.054 61.792,42.054 62.135,41.711 62.411,41.711 71.73,32.392 80.01,32.392 CN2.14@81.28,31.122
  Bottom Layer w0.127: CN3.22@34.127,38.515 34.8,38.515 35.453,39.168 v1(39.034,39.168) 39.902,38.3 43.062,38.3 44.962,40.2 45.596,40.2 R32.2@45.854,39.942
